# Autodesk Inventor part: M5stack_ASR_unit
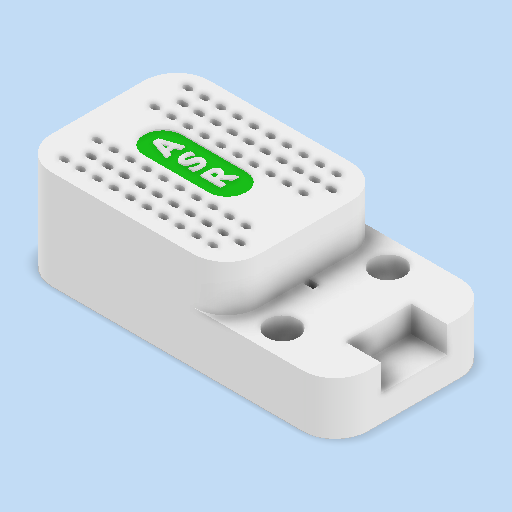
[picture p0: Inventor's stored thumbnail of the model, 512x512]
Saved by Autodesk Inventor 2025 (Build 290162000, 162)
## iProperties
Created: 2025-03
Part Number: M5stack_ASR_unit
Material: Plastica ABS
Document SubType Name: Modeling
Designer: Ryzen5700u
Density: 1.06 g/cm^3
Appearance: Bianco
Author: Ryzen5700u
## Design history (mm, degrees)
sketch "Schizzo1"
  geometry: L1 (24, -12)-(-24, -12); L2 (-24, -12)-(-24, 12); L3 (-24, 12)-(24, 12); L4 (24, 12)-(24, -12); L5 (24, -12)-(-24, 12); L6 (-24, -12)-(24, 12); 1 further point
  constraints: 12 end point, 2 midpoint, 2 parallel, 1 horizontal, 1 perpendicular
  dimensions: "d0" = 48 distance of L2.end L3.end; "d1" = 24 distance of L1.end L2.end
extrude "Estrusione1" new body sketch "Schizzo1" distance "d2" = 15; taper "d3" = 0 deg
sketch "Schizzo2"
  geometry: L1 (-24, -12)-(24, -12) reference; L2 (7.5, -12)-(7.5, 12); L3 (24, 12)-(-24, 12) reference; L4 (-24, 12)-(-24, -12) reference; L5 (-24, -12)-(24, -12) reference; L6 (24, -12)-(24, 12) reference; L7 (24, 12)-(-24, 12) reference; L8 (-24, 12)-(-24, -12) reference; 3 further points
  constraints: 2 end point, 2 point on line, 1 vertical
  dimensions: "d4" = 31.5 distance between parallel lines of L4 L2
extrude "Estrusione2" cut sketch "Schizzo2" distance "d5" = 7; taper "d6" = 0 deg
sketch "Schizzo3" dims "d8" = 4.8
  geometry: L1 (-24, -12)-(24, -12) reference; L2 (12, -12)-(12, 12.011); L3 (24, 12)-(24, -12) reference; L4 (24, 0)-(7.5, 0); L5 (7.5, -12)-(7.5, 12) reference; 6 further points
  constraints: 4 end point, 4 point on line, 2 midpoint, 2 vertical alignment, 1 coincident, 1 horizontal, 1 symmetric about line, 1 vertical, 4 other
  dimensions: "d7" = 12 distance between parallel lines of L3 L2; "d9" = 20.8 distance of point (12, 10.4) point (12, -10.4)
extrude "Estrusione3" cut sketch "Schizzo3" extent not by distance; stored distance "d10" = 0; taper "d11" = 0 deg
fillet "Raccordo1" dims "d12" = 5
sketch "Schizzo4"
  geometry: L1 (18.5, -5)-(29.5, -5); L2 (29.5, -5)-(29.5, 5); L3 (29.5, 5)-(18.5, 5); L4 (18.5, 5)-(18.5, -5); L5 (24, 7)-(24, -7) reference; L6 (18.5, -5)-(29.5, 5); L7 (29.5, -5)-(18.5, 5); 4 further points
  constraints: 12 end point, 3 midpoint, 2 parallel, 1 horizontal, 1 perpendicular
  dimensions: "d13" = 11 distance of L3.end L2.end; "d14" = 10 distance of L2.end L1.end
extrude "Estrusione4" cut sketch "Schizzo4" distance "d15" = 4; taper "d16" = 0 deg
sketch "Schizzo5"
  geometry: L1 (-4.465, 0.111)-(-14.219, 0.111); L2 (-4.465, 2.972)-(-14.219, 2.972); L3 (-14.219, -2.75)-(-4.465, -2.75); A1 r 2.861 centre (-4.465, 0.111) between (-4.465, -2.75) and (-4.465, 2.972); A2 r 2.861 centre (-14.219, 0.111) between (-14.219, 2.972) and (-14.219, -2.75); 2 further points
  constraints: 8 end point, 4 point on circle, 4 tangent, 2 centre point, 1 horizontal, 1 midpoint, 1 parallel
extrude "Estrusione5" cut sketch "Schizzo5" distance "d17" = 0.2; taper "d18" = 0 deg
sketch "Schizzo6"
  geometry: L1 (-19.994, -9.352)-(-19.405, -9.352); L2 (-19.994, -9.768)-(-19.405, -9.768); L3 (-19.405, -8.935)-(-19.994, -8.935); A1 r 0.417 centre (-19.994, -9.352) between (-19.994, -8.935) and (-19.994, -9.768); A2 r 0.417 centre (-19.405, -9.352) between (-19.405, -9.768) and (-19.405, -8.935); 2 further points
  constraints: 8 end point, 4 point on circle, 4 tangent, 2 centre point, 1 horizontal, 1 midpoint, 1 parallel
extrude "Estrusione6" cut sketch "Schizzo6" distance "d19" = 1; taper "d20" = 0 deg
sketch "Schizzo7"
  geometry: L1 (-18.447, -6.939)-(-17.675, -6.939); L2 (-18.447, -7.349)-(-17.675, -7.349); L3 (-17.675, -6.529)-(-18.447, -6.529); A1 r 0.41 centre (-18.447, -6.939) between (-18.447, -6.529) and (-18.447, -7.349); A2 r 0.41 centre (-17.675, -6.939) between (-17.675, -7.349) and (-17.675, -6.529); 2 further points
  constraints: 8 end point, 4 point on circle, 4 tangent, 2 centre point, 1 horizontal, 1 midpoint, 1 parallel
extrude "Estrusione8" cut sketch "Schizzo7" distance "d29" = 1; taper "d30" = 0 deg
pattern_linear "Serie rettangolare2" dims "d33" = 2.5
mirror "Speculare1"
sketch "Schizzo8"
  geometry: 1 further point
sketch "Schizzo9"
  geometry: L1 (5.847, -0.5)-(9.153, -0.5); L2 (9.153, -0.5)-(9.153, 0.5); L3 (9.153, 0.5)-(5.847, 0.5); L4 (5.847, 0.5)-(5.847, -0.5); L5 (7.5, -7)-(7.5, 7) reference; L6 (5.847, -0.5)-(9.153, 0.5); L7 (9.153, -0.5)-(5.847, 0.5); 4 further points
  constraints: 12 end point, 3 midpoint, 2 parallel, 1 horizontal, 1 perpendicular
  dimensions: "d34" = 1 distance of L2.end L1.end
extrude "Estrusione9" cut sketch "Schizzo9" distance "d35" = 1; taper "d36" = 0 deg
sketch "Schizzo10"
  geometry: L1 (-15.363, -1.38)-(-15.363, 1.665); L2 (-15.363, 1.665)-(-2.269, 1.665); L3 (-2.269, 1.665)-(-2.269, -1.38); L4 (-2.269, -1.38)-(-15.363, -1.38); 1 further point
  constraints: 2 other
extrude "Estrusione10" join sketch "Schizzo10" distance "d37" = 0.2; taper "d38" = 0 deg
node "Solido1"
pattern_linear "Serie rettangolare1" dims "d23" = 2.5, "d26" = 5
node "Linea chiusa proiettata1"
